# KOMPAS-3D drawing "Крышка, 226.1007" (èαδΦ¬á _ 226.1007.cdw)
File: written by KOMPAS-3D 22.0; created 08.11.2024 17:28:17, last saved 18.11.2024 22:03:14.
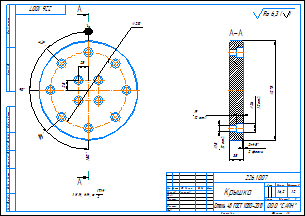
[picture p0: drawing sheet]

Sheet 1: A3, landscape

Document properties: Автор: aleksander.larionov.10@gmail.com; Полное имя файла: C:\Мои папки\Работа\Крышки, фланцы\226.1007\Крышка _ 226.1007.cdw; Знак неуказанной шероховатости: 4; Параметр неуказанной шероховатости: Ra 6,3; Масса: 16.202065

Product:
- Part/product: Крышка  | designation 226.1007
    Материал: Сталь 45 ГОСТ 1050-2013 (density 7810 kg/m3)
    Масса: 16.202065

Title block, sheet 1: Наименование: Крышка; designation: 226.1007; Материал: Сталь 45 ГОСТ 1050-2013; Масса: 16,2; Количество листов документа: 1; organisation: ООО "САЙН"; Форматы листов документа: A3; stored path: C:\Users\aleks\Desktop\Работа\Крышки, фланцы\226.1007\Крышка _ 226.1007.cdw; Разработал: Ларионов

Views: Вид 1, Сверху, Разрез А-А
Referenced files in C:\Users\aleks\Desktop\Работа\Крышки, фланцы\226.1007\: Крышка _ 226.1007.m3d
Referenced files in C:\Мои папки\Работа\Крышки, фланцы\226.1007\: Крышка _ 226.1007.m3d
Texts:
  Ra 6,3
  Ra 6,3 ( )
Dimensions and other numbers on the sheet: 210; 135; 180; 28; 1 H14, h14,    IT14 2 .; 3; 226.1007; 275; 38; 2; 2 фаски; 19; 12 отв.; 18; 26; 5; 1:2; 1; 16,2; 226.1007 Крышка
